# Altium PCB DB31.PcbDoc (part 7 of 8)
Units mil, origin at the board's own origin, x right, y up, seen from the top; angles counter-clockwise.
Board outline 3236.22 x 4456.69 mil, 8 copper layers (Top Layer, MidLayer1, MidLayer2, GND-Layer5, MidLayer3, VCC, MidLayer4, Bottom Layer), stack 61.8 mil thick; 226 components, 469 nets, 1815 pads, 1562 vias.
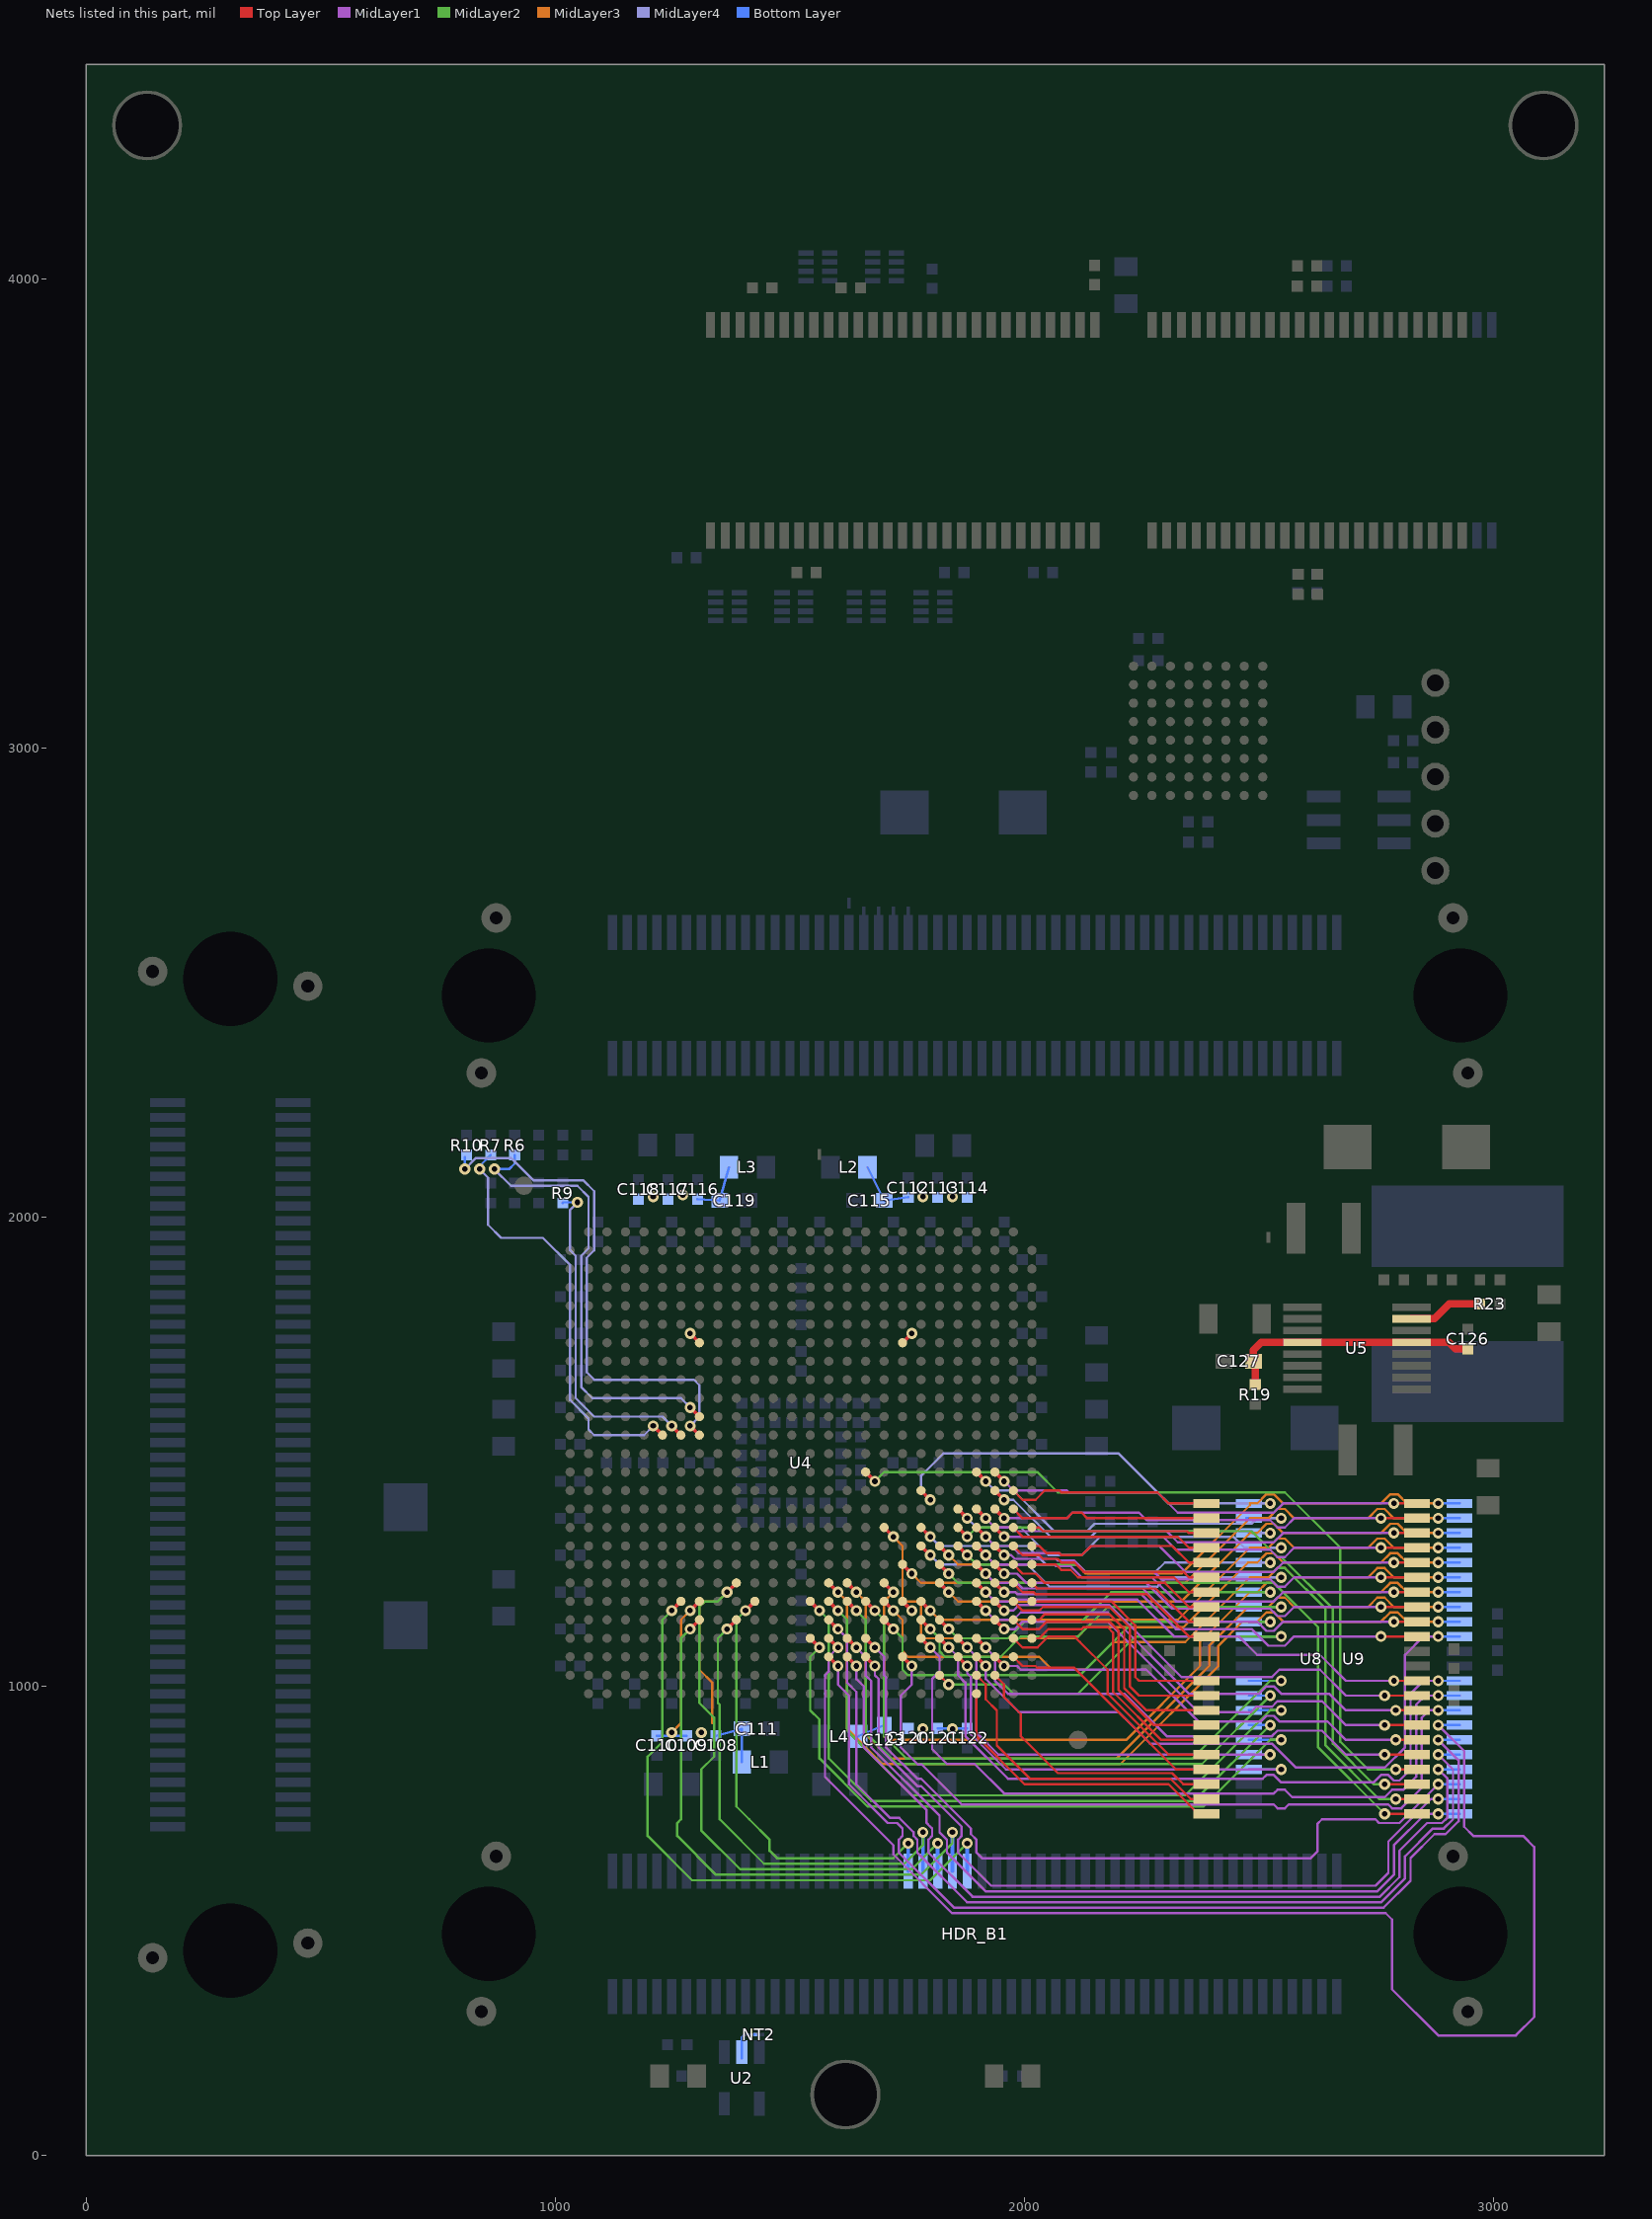
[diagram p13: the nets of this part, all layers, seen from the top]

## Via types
v1: diameter 23.62, hole 11.81, Top Layer to Bottom Layer, 947 vias
v2: diameter 23.62, hole 11.81, Top Layer to Bottom Layer, tented both sides, 476 vias
v3: diameter 27.56, hole 15.75, Top Layer to Bottom Layer, 138 vias
v4: diameter 23.62, hole 11.81, Top Layer to Bottom Layer, tented top, 1 vias

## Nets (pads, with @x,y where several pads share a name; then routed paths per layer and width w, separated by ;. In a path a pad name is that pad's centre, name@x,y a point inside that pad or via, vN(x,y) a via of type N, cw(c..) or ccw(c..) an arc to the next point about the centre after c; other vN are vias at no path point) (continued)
SRAM1_A3: U4.AD22 U9.4 | length 938
  Top Layer w7.87: U4.AD22@1858.27,1062.99 v1(1877.95,1043.3)
  MidLayer1 w5: v1(1877.95,1043.3) 1877.95,1027.56 1885.83,1019.68 1885.83,921.26 1885.83,909.45 1885.83,897.64 1960.63,822.83 v1(2547.24,822.83)
  Bottom Layer w5: U9.4@2478.44,822.83 v1(2547.24,822.83)
SRAM1_A4: U4.AC22 U9.5 | length 907.8
  Top Layer w7.87: U4.AC22@1858.27,1102.36 v1(1877.96,1082.67)
  MidLayer1 w5: v1(1877.96,1082.67) 1897.64,1062.99 1897.64,921.26 1897.64,909.45 1897.64,901.57 1944.88,854.33 v1(2523.62,854.33)
  Bottom Layer w5: U9.5@2478.44,854.32 v1(2523.62,854.33)
SRAM1_A5: U4.U20 U9.18 | length 840.9
  Top Layer w7.87: U4.U20@1779.53,1338.58 v1(1799.22,1318.9)
  MidLayer4 w5: v1(1799.22,1318.9) 1818.9,1299.21 2005.91,1299.21 2045.27,1259.84 2078.74,1259.84 2090.55,1259.84 2114.17,1259.84 2129.92,1244.09 2279.53,1244.09 2299.2,1263.77 v1(2523.83,1263.77)
  Bottom Layer w5: U9.18@2478.44,1263.77 v1(2523.83,1263.77) v1@2527.77,1263.77
SRAM1_A6: U4.T22 U9.19 | length 828.6
  Top Layer w7.87: U4.T22@1858.27,1377.95 v1(1877.96,1358.27)
  MidLayer4 w5: v1(1877.96,1358.27) 1897.64,1338.58 1992.13,1338.58 2051.18,1279.53 2078.74,1279.53 2090.55,1279.53 2122.05,1279.53 2161.42,1318.9 2444.88,1318.9 2468.5,1295.28 v1(2547.24,1295.28)
  Bottom Layer w5: U9.19@2478.44,1295.27 v1(2547.24,1295.28) v1@2551.18,1295.28
SRAM1_A7: U4.R24 U9.20 | length 683.4
  Top Layer w7.87: U4.R24@1937.01,1417.32 v1(1956.7,1397.64)
  MidLayer4 w5: v1(1956.7,1397.64) 1976.38,1397.64 2055.12,1318.9 2078.74,1318.9 2090.55,1318.9 2141.73,1318.9 2153.54,1330.71 2484.25,1330.71 2488.2,1326.76 v1(2523.83,1326.76)
  Bottom Layer w5: U9.20@2478.44,1326.76 v1(2523.83,1326.76) v1@2527.77,1326.76
SRAM1_A8: U4.P23 U9.21 | length 791.9
  Top Layer w7.87: U4.P23@1897.64,1456.69 v1(1917.33,1437.01)
  MidLayer4 w5: v1(1917.33,1437.01) 1937.01,1417.32 1976.38,1417.32 2062.99,1330.71 2078.74,1330.71 2090.55,1330.71 2133.86,1330.71 2149.61,1346.46 2484.25,1346.46 2496.06,1358.27 v1(2547.24,1358.27)
  Bottom Layer w5: U9.21@2472.44,1358.27 U9.21@2478.44,1358.26 v1(2547.24,1358.27) v1@2551.18,1358.27
SRAM1_A9: U4.R20 U9.22 | length 940.5
  Top Layer w7.87: U4.R20@1779.53,1417.32 v1(1799.22,1397.64)
  MidLayer4 w5: v1(1799.22,1397.64) 1779.53,1417.32 1779.53,1448.82 1826.77,1496.06 2078.74,1496.06 2090.55,1496.06 2200.79,1496.06 2307.1,1389.75 v1(2523.83,1389.75)
  Bottom Layer w5: U9.22@2478.44,1389.75 v1(2523.83,1389.75)
SRAM1_A10: U4.V21 U9.23 | length 1229.9
  Top Layer w7.87: U4.V21@1818.9,1299.21 v1(1838.59,1279.53)
  MidLayer3 w5: v1(1838.59,1279.53) 1858.27,1259.84 2078.74,1259.84 2090.55,1259.84 2110.24,1259.84 2129.92,1240.16 2334.65,1240.16 2480.33,1385.84 2480.33,1389.75 2496.27,1389.75 2515.96,1409.44 2531.7,1409.44 2551.38,1389.76 ; 2551.18,1389.76 2551.38,1389.76 ; v1(2881.9,1389.75) 2814.97,1389.75 2795.28,1409.45 2779.53,1409.45 2759.84,1389.76 2551.38,1389.76
  Bottom Layer w5: v1(2881.9,1389.75) U9.23@2927.25,1389.75
SRAM1_A11: U4.W19 U9.24 | length 1292.8
  Top Layer w7.87: U4.W19@1740.16,1259.84 v1(1759.84,1240.16)
  MidLayer3 w5: v1@1760.03,1239.97 1779.53,1220.47 2078.74,1220.47 2090.55,1220.47 2342.52,1220.47 2480.31,1358.27 2519.69,1358.27 2539.37,1377.95 2555.12,1377.95 2574.8,1358.27 2732.28,1358.27 2751.97,1377.95 2767.72,1377.95 2787.41,1358.26 v1(2881.9,1358.26)
  Bottom Layer w5: v1(2881.9,1358.26) U9.24@2927.25,1358.26
SRAM1_A12: U4.Y21 U9.25 | length 1217.6
  Top Layer w7.87: U4.Y21@1818.9,1220.47 v1(1838.58,1200.78)
  MidLayer3 w5: v1(1838.58,1200.78) 1858.27,1181.1 2078.74,1181.1 2090.55,1181.1 2334.67,1181.1 2480.33,1326.76 2496.27,1326.76 2515.96,1346.45 2531.7,1346.45 2551.38,1326.77 2759.84,1326.77 2779.53,1346.46 2795.28,1346.46 2814.97,1326.76 v1(2881.9,1326.76)
  Bottom Layer w5: v1(2881.9,1326.76) U9.25@2927.25,1326.76
SRAM1_A13: U4.AA20 U9.26 | length 1260.3
  Top Layer w7.87: U4.AA20@1779.53,1181.1 v1(1799.22,1161.41)
  MidLayer3 w5: v1(1799.22,1161.41) 1818.9,1141.73 2078.74,1141.73 2090.55,1141.73 2326.77,1141.73 2480.31,1295.28 2519.69,1295.28 2539.37,1314.96 2555.12,1314.96 2574.8,1295.28 2732.28,1295.28 2751.97,1314.96 2767.72,1314.96 2787.41,1295.27 v1(2881.9,1295.27)
  Bottom Layer w5: v1(2881.9,1295.27) U9.26@2927.25,1295.27
SRAM1_A14: U4.U18 U9.27 | length 1525.3
  Top Layer w7.87: U4.U18@1700.79,1338.58 v1(1720.47,1318.9)
  MidLayer3 w5: v1(1720.47,1318.9) 1740.16,1299.21 1740.16,1188.98 1748.03,1181.1 1771.65,1181.1 1779.53,1173.23 1779.53,1110.24 1787.4,1102.36 2078.74,1102.36 2090.55,1102.36 2110.24,1102.36 2133.86,1125.98 2338.58,1125.98 2476.37,1263.77 2496.27,1263.77 2515.96,1283.45 2531.7,1283.45 2551.38,1263.78 2759.84,1263.78 2779.53,1283.46 2795.28,1283.46 2814.97,1263.77 v1(2881.9,1263.77)
  Bottom Layer w5: v1(2881.9,1263.77) U9.27@2927.25,1263.77
SRAM1_A15: U4.AC17 U9.42 | length 1700
  Top Layer w7.87: U4.AC17@1661.42,1102.36 v1(1681.1,1082.67)
  MidLayer1 w5: v1(1681.1,1082.67) 1700.79,1062.99 1700.79,1023.62 1704.72,1019.68 1704.72,921.26 1704.72,909.45 1704.72,870.08 1771.65,803.15 1779.53,803.15 1885.83,696.85 1885.83,685.04 1897.64,673.23 1897.64,645.67 1909.45,633.86 2610.24,633.86 2624.26,647.88 2624.26,706.94 2633.86,716.54 2748.03,716.54 2755.91,708.66 2799.21,708.66 v1(2881.9,791.33)
  Bottom Layer w5: v1(2881.9,791.33) U9.42@2927.25,791.33
SRAM1_A16: U4.AD17 U9.43 | length 1724
  Top Layer w7.87: U4.AD17@1661.42,1062.99 v1(1681.1,1043.3)
  MidLayer1 w5: v1(1681.1,1043.3) 1681.1,1023.62 1688.98,1015.75 1688.98,921.26 1688.98,909.45 1688.98,870.08 1771.65,787.4 1779.53,787.4 1866.14,700.79 1866.14,681.1 1858.27,673.23 1858.27,645.67 1928.89,575.05 2748.28,575.05 2775.59,602.36 2775.59,669.29 2866.13,759.83 v1(2881.9,759.83)
  Bottom Layer w5: v1(2881.9,759.83) U9.43@2927.25,759.83
SRAM1_A17: U4.AC16 U9.44 | length 1776.8
  Top Layer w7.87: U4.AC16@1622.05,1102.36 v1(1641.73,1082.67)
  MidLayer1 w5: v1(1641.73,1082.67) 1661.42,1062.99 1661.42,1023.62 1673.23,1011.81 1673.23,921.26 1673.23,909.45 1673.23,870.08 1818.9,724.41 1818.9,688.98 1834.65,673.23 1834.65,645.67 1917.08,563.24 2752.21,563.24 2787.4,598.43 2787.4,661.42 2854.32,728.34 v1(2881.9,728.34)
  Bottom Layer w5: v1(2881.9,728.34) U9.44@2927.25,728.34
SRAM1_A18: U4.AA18 U9.28 | length 1440.2
  Top Layer w7.87: U4.AA18@1700.79,1181.1 v1(1720.47,1161.41)
  MidLayer3 w5: v1(1720.47,1161.41) 1740.16,1141.73 1740.16,1074.8 1751.97,1062.99 2031.5,1062.99 2059.05,1035.43 2078.74,1035.43 2090.55,1035.43 2129.92,1035.43 2188.98,1094.49 2342.52,1094.49 2480.31,1232.28 2519.69,1232.28 2539.37,1251.97 2555.12,1251.97 2574.8,1232.28 2732.28,1232.28 2751.97,1251.97 2767.72,1251.97 2787.41,1232.28 v1(2881.9,1232.27)
  Bottom Layer w5: v1(2881.9,1232.27) U9.28@2927.25,1232.27
SRAM1_D0: U4.AA14 U9.7 | length 1445.8
  Top Layer w7.87: U4.AA14@1543.31,1181.1 v1(1562.99,1161.41)
  MidLayer2 w5: v1(1562.99,1161.41) 1582.68,1141.73 1582.68,921.26 1582.68,909.45 1582.68,846.46 1673.23,755.91 2362.2,755.91 2523.6,917.3 v1(2523.83,917.3)
  Bottom Layer w5: U9.7@2478.44,917.31 v1(2523.83,917.3) v1@2527.77,917.3
SRAM1_D1: U4.AA15 U9.8 | length 1421.9
  Top Layer w7.87: U4.AA15@1582.68,1181.1 v1(1602.36,1161.41)
  MidLayer2 w5: v1(1602.36,1161.41) 1622.05,1141.73 1622.05,921.26 1622.05,909.45 1622.05,905.51 1759.84,767.72 2342.52,767.72 2523.62,948.82 v1(2547.24,948.82)
  Bottom Layer w5: U9.8@2478.44,948.81 v1(2547.24,948.82) v1@2551.18,948.82
SRAM1_D2: U4.AA16 U9.9 | length 1295.9
  Top Layer w7.87: U4.AA16@1622.05,1181.1 v1(1641.73,1161.41)
  MidLayer2 w5: v1(1641.73,1161.41) 1661.42,1141.73 1661.42,921.26 1661.42,909.45 1661.42,901.57 1728.35,834.65 2378.17,834.65 v1(2523.83,980.31) v1@2523.61,980.31
  Bottom Layer w5: U9.9@2478.44,980.31 v1(2523.83,980.31) v1@2527.77,980.31
SRAM1_D3: U4.AA17 U9.10 | length 1311
  Top Layer w7.87: U4.AA17@1661.42,1181.1 v1(1681.1,1161.41)
  MidLayer2 w5: v1(1681.1,1161.41) 1700.79,1141.73 1700.79,921.26 1700.79,909.45 1700.79,893.7 1748.03,846.46 2358.27,846.46 2523.62,1011.81 v1(2547.24,1011.81)
  Bottom Layer w5: U9.10@2478.44,1011.8 v1(2547.24,1011.81) v1@2551.18,1011.81
SRAM1_D4: U4.AE21 U9.13 | length 868
  Top Layer w5: U4.AE21@1818.9,1023.62 v1(1838.58,1003.94)
  MidLayer2 w5: v1(1838.58,1003.94) 1956.69,1003.94 1976.38,984.25 2078.74,984.25 2090.55,984.25 2114.17,984.25 2236.22,1106.3 v1(2547.24,1106.3)
  Bottom Layer w5: U9.13@2478.44,1106.29 v1(2547.24,1106.3) v1@2551.18,1106.3
SRAM1_D5: U4.AB18 U9.14 | length 1007.8
  Top Layer w7.87: U4.AB18@1700.79,1141.73 v1(1720.47,1122.04)
  MidLayer2 w5: v1(1720.47,1122.04) 1740.16,1102.36 1740.16,1035.43 1751.97,1023.62 2078.74,1023.62 2090.55,1023.62 2118.11,1023.62 2232.27,1137.79 v1(2523.83,1137.79)
  Bottom Layer w5: U9.14@2478.44,1137.79 v1(2523.83,1137.79) v1@2527.77,1137.79
SRAM1_D6: U4.AB20 U9.15 | length 933.2
  Top Layer w7.87: U4.AB20@1779.53,1141.73 v1(1799.21,1122.04)
  MidLayer2 w5: v1(1799.21,1122.04) 1818.9,1102.36 1818.9,1074.8 1830.71,1062.99 1948.82,1062.99 1992.13,1106.3 2078.74,1106.3 2090.55,1106.3 2114.17,1106.3 2177.17,1169.29 v1(2547.24,1169.29)
  Bottom Layer w5: U9.15@2478.44,1169.28 v1(2547.24,1169.29) v1@2551.18,1169.29
SRAM1_D7: U4.AB21 U9.16 | length 811.3
  Top Layer w7.87: U4.AB21@1818.9,1141.73 v1(1838.58,1122.04)
  MidLayer2 w5: v1(1838.58,1122.04) 1858.27,1102.36 1964.57,1102.36 2000,1137.8 2078.74,1137.8 2090.55,1137.8 2122.05,1137.8 2185.04,1200.79 v1@2523.83,1200.79
  Bottom Layer w5: U9.16@2478.44,1200.78 v1(2523.83,1200.78) v1@2527.77,1200.78
SRAM1_D8: U4.Y18 U9.29 | length 1765.9
  Top Layer w7.87: U4.Y18@1700.79,1220.47 v1(1720.47,1200.78)
  MidLayer3 w5: v1(1720.47,1200.78) 1700.79,1181.1 1700.79,921.26 1700.79,909.45 1700.79,893.7 1708.66,885.83 2216.54,885.83 2374.02,1043.31 2374.02,1094.49 2480.3,1200.78 2496.27,1200.78 2515.96,1220.46 2531.7,1220.46 2551.38,1200.79 2759.84,1200.79 2779.53,1220.47 2795.28,1220.47 2814.97,1200.78 v1(2881.9,1200.78)
  Bottom Layer w5: v1(2881.9,1200.78) U9.29@2927.25,1200.78
SRAM1_D9: U4.Y16 U9.30 | length 1817.9
  Top Layer w7.87: U4.Y16@1622.05,1220.47 v1(1641.73,1200.78)
  MidLayer3 w5: v1(1641.73,1200.78) 1661.42,1181.1 1661.42,921.26 1661.42,909.45 1661.42,897.64 1712.6,846.46 2196.85,846.46 2393.7,1043.31 2393.7,1086.61 2476.38,1169.29 2519.69,1169.29 2539.37,1188.98 2555.12,1188.98 2574.8,1169.29 2732.28,1169.29 2751.97,1188.98 2767.72,1188.98 2787.41,1169.29 v1(2881.9,1169.28)
  Bottom Layer w5: v1(2881.9,1169.28) U9.30@2927.25,1169.28
SRAM1_D10: U4.Y15 U9.31 | length 1847.1
  Top Layer w7.87: U4.Y15@1582.68,1220.47 v1(1602.36,1200.78)
  MidLayer3 w5: v1(1602.36,1200.78) 1622.05,1181.1 1622.05,921.26 1622.05,909.45 1696.85,834.65 2204.72,834.65 2413.39,1043.31 2413.39,1086.61 2464.56,1137.79 2496.27,1137.79 2515.96,1157.47 2531.7,1157.47 2551.38,1137.8 2759.84,1137.8 2779.53,1157.48 2795.28,1157.48 2814.97,1137.79 v1(2881.9,1137.79)
  Bottom Layer w5: v1(2881.9,1137.79) U9.31@2927.25,1137.79
SRAM1_D11: U4.AD23 U9.32 | length 1379
  Top Layer w7.87: U4.AD23@1897.64,1062.99 v1(1917.33,1043.3)
  MidLayer1 w5: v1(1917.33,1043.3) 1917.33,1015.75 1988.19,944.88 2078.74,944.88 2090.55,944.88 2200.79,944.88 2267.72,877.95 2527.56,877.95 2578.75,826.76 2767.71,826.76 2811.02,870.08 2811.02,1066.93 2850.39,1106.3 2858.27,1106.3 2862.59,1106.3 ; 2858.28,1106.29 v1(2881.9,1106.29)
  Bottom Layer w5: v1(2881.9,1106.29) U9.32@2927.25,1106.29
SRAM1_D12: U4.AC21 U9.35 | length 1526.1
  Top Layer w7.87: U4.AC21@1818.9,1102.36 v1(1838.59,1082.67)
  MidLayer1 w5: v1(1838.59,1082.67) 1858.27,1062.99 1858.27,1023.62 1874.02,1007.87 1874.02,921.26 1874.02,909.45 1874.02,893.7 1964.57,803.15 2507.87,803.15 2515.75,811.02 2531.5,811.02 2547.24,795.28 2744.09,795.27 2759.84,811.02 2775.6,811.02 2787.4,799.21 2799.21,799.21 2822.83,822.83 2822.83,984.25 2850.39,1011.81 2862.2,1011.81 ; 2862.21,1011.8 v1(2881.9,1011.8)
  Bottom Layer w5: v1(2881.9,1011.8) U9.35@2927.25,1011.8
SRAM1_D13: U4.AC20 U9.36 | length 1611.7
  Top Layer w7.87: U4.AC20@1779.53,1102.36 v1(1799.22,1082.67)
  MidLayer1 w5: v1(1799.22,1082.67) 1818.9,1062.99 1818.9,1031.5 1803.15,1015.75 1803.15,921.26 1803.15,909.45 1803.15,866.14 1834.65,834.65 1893.7,834.65 1956.69,771.65 2531.5,771.65 2539.37,779.53 2555.12,779.53 2570.87,763.78 2767.71,763.77 2783.46,779.52 2807.08,779.52 2834.65,807.09 2834.65,960.63 2854.33,980.32 2862.2,980.32 v1(2881.9,980.31)
  Bottom Layer w5: v1(2881.9,980.31) U9.36@2927.25,980.31
SRAM1_D14: U4.AD19 U9.37 | length 1636.3
  Top Layer w7.87: U4.AD19@1740.16,1062.99 v1(1759.84,1043.3)
  MidLayer1 w5: v1(1759.84,1043.3) 1759.84,1003.94 1736.22,980.32 1736.22,921.26 1736.22,909.45 1736.22,870.08 1772.88,833.42 1780.75,833.42 1827.76,786.42 1866.14,748.03 2531.5,748.03 2539.37,740.16 2555.12,740.16 2562.99,748.03 2775.59,748.03 2783.46,740.16 2803.15,740.16 2846.46,783.46 2846.46,933.07 2862.2,948.82 v1(2881.9,948.81)
  Bottom Layer w5: v1(2881.9,948.81) U9.37@2927.25,948.81
SRAM1_D15: U4.AC15 U9.38 | length 2984.3
  Top Layer w7.87: U4.AC15@1582.68,1102.36 v1(1602.36,1082.67)
  MidLayer1 w5: v1(1602.36,1082.67) 1582.68,1062.99 1582.68,1031.5 1574.8,1023.62 1574.8,921.26 1574.8,909.45 1574.8,807.09 1720.47,661.42 1720.47,641.73 1845.47,516.73 2769.68,516.73 2783.46,502.95 2783.46,354.33 2881.89,255.91 3047.24,255.91 3086.61,295.28 3086.61,657.48 3062.99,681.1 2956.69,681.1 2937.01,700.79 2937.01,862.2 v1(2881.9,917.31)
  Bottom Layer w5: v1(2881.9,917.31) U9.38@2927.25,917.31
SRAM1_NBHE: U4.AB15 U9.40 | length 2068.3
  Top Layer w7.87: U4.AB15@1582.68,1141.73 v1(1602.36,1122.04)
  MidLayer1 w5: v1(1602.36,1122.04) 1622.05,1102.36 1622.05,1007.87 1641.73,988.19 1641.73,921.26 1641.73,909.45 1641.73,791.34 1713.58,719.49 1733.27,719.49 1763.78,688.98 1763.78,681.1 1771.65,673.23 1771.65,645.67 1877.21,540.11 2760.58,540.11 2811.02,590.55 2811.02,637.79 2870.08,696.85 2893.7,696.85 2913.39,716.54 2913.39,822.83 v1(2881.9,854.32)
  Bottom Layer w5: v1(2881.9,854.32) U9.40@2927.25,854.32
SRAM1_NBLE: U4.AD15 U9.39 | length 2079.8
  Top Layer w7.87: U4.AD15@1582.68,1062.99 v1(1602.36,1043.3)
  MidLayer1 w5: v1(1602.36,1043.3) 1602.36,1003.93 1620.15,986.15 1625.98,980.31 1625.98,921.26 1625.98,909.45 1625.98,791.34 1708.66,708.66 1728.35,708.66 1740.16,696.85 1740.16,681.1 1732.28,673.23 1732.28,645.67 1849.41,528.54 2765.75,528.54 2822.83,585.63 2822.83,633.86 2874.02,685.04 2897.64,685.04 2925.2,712.6 2925.2,842.52 v1(2881.9,885.82)
  Bottom Layer w5: v1(2881.9,885.82) U9.39@2927.25,885.82
SRAM1_NCS: U4.AC14 U9.6 | length 1438.5
  Top Layer w7.87: U4.AC14@1543.31,1102.36 v1(1562.99,1082.67)
  MidLayer2 w5: v1(1562.99,1082.67) 1543.31,1062.99 1543.31,948.82 1562.99,929.13 1562.99,921.26 1562.99,909.45 1562.99,846.46 1665.35,744.09 2381.89,744.09 2523.62,885.83 v1(2547.24,885.83)
  Bottom Layer w5: U9.6@2478.44,885.82 v1(2547.24,885.83) v1@2551.18,885.83
SRAM1_NOE: U4.AD16 U9.41 | length 1899.5
  Top Layer w7.87: U4.AD16@1622.05,1062.99 v1(1641.73,1043.3)
  MidLayer1 w5: v1(1641.73,1043.3) 1641.74,1015.75 1657.48,1000 1657.48,921.26 1657.48,909.45 1657.48,870.08 1791.34,736.22 1791.34,708.66 1799.21,700.79 1803.15,696.85 1803.15,681.1 1795.28,673.23 1795.28,645.67 1889.27,551.67 2757.38,551.67 2799.21,593.5 2799.21,649.61 2858.27,708.66 2889.76,708.66 2901.57,720.47 2901.57,803.15 v1(2881.9,822.83)
  Bottom Layer w5: v1(2881.9,822.83) U9.41@2927.25,822.83
SRAM1_NWE: U4.V20 U9.17 | length 884.5
  Top Layer w7.87: U4.V20@1779.53,1299.21 v1(1799.22,1279.53)
  MidLayer4 w5: v1(1799.22,1279.53) 1818.9,1259.84 2005.91,1259.84 2053.15,1212.6 2078.74,1212.6 2090.55,1212.6 2283.46,1212.6 2303.15,1232.28 v1(2547.24,1232.28)
  Bottom Layer w5: U9.17@2478.44,1232.28 v1(2547.24,1232.28) v1@2551.18,1232.28
SRAM2_A0: U4.W21 U8.1 | length 1387.9
  Top Layer w5: v1(2767.69,728.34) U8.1@2836.71,728.34
  Top Layer w7.87: U4.W21@1818.9,1259.84 v1(1838.59,1240.16)
  MidLayer2 w5: v1(1838.59,1240.16) 1858.27,1220.47 2078.74,1220.47 2090.55,1220.47 2531.5,1220.47 2625.98,1125.98 2625.98,870.08 v1(2767.69,728.34)
SRAM2_A1: U4.V22 U8.2 | length 1379
  Top Layer w5: v1(2791.34,759.84) U8.2@2836.71,759.83
  Top Layer w7.87: U4.V22@1858.27,1299.21 v1(1877.96,1279.53)
  MidLayer2 w5: v1(1877.96,1279.53) 1897.64,1259.84 2078.74,1259.84 2090.55,1259.84 2114.17,1259.84 2129.92,1244.09 2531.5,1244.09 2539.37,1251.97 2555.12,1251.97 2641.73,1165.35 2641.73,874.02 2755.91,759.84 v1(2791.34,759.84)
SRAM2_A2: U4.U22 U8.3 | length 1389.8
  Top Layer w5: v1(2767.69,791.34) U8.3@2836.71,791.33
  Top Layer w7.87: U4.U22@1858.27,1338.58 v1(1877.96,1318.9)
  MidLayer2 w5: v1(1877.96,1318.9) 1897.64,1338.58 2025.59,1338.58 2033.47,1330.71 2078.74,1330.71 2090.55,1330.71 2484.25,1330.71 2539.37,1275.59 2547.24,1275.59 2657.48,1165.35 2657.48,877.95 2744.1,791.34 v1(2767.69,791.34)
SRAM2_A3: U4.P17 U8.4 | length 1696.3
  Top Layer w5: v1(2791.34,822.83) U8.4@2836.71,822.83
  Top Layer w7.87: U4.P17@1661.42,1456.69 v1(1681.1,1437.01)
  MidLayer2 w5: v1(1681.1,1437.01) 1700.79,1456.69 2027.56,1456.69 2070.87,1413.39 2078.74,1413.39 2090.55,1413.39 2555.12,1413.39 2673.23,1295.28 2673.23,881.89 2732.28,822.83 v1(2791.34,822.83)
SRAM2_A4: U4.AC23 U8.5 | length 1101.6
  Top Layer w5: v1(2767.69,854.33) U8.5@2836.71,854.32
  Top Layer w7.87: U4.AC23@1897.64,1102.36 v1(1917.33,1082.67)
  MidLayer1 w5: v1@2759.84,854.31 2685.04,854.31 2633.86,905.51 2539.37,905.51 2527.56,893.7 2303.15,893.7 2212.6,984.25 2090.55,984.25 2078.74,984.25 1964.57,984.25 1937.01,1011.81 1937.01,1062.99 ; 1937.01,1062.99 v1(1917.33,1082.67) 1937.01,1062.99
SRAM2_A5: U4.U23 U8.18 | length 1002.7
  Top Layer w5: v1@2787.4,1263.77 U8.18@2836.71,1263.77
  Top Layer w7.87: U4.U23@1897.64,1338.58 v1(1917.33,1318.9)
  MidLayer1 w5: v1(1917.33,1318.9) 1937.01,1299.21 1972.44,1299.21 1988.19,1283.46 2074.8,1283.46 2078.74,1279.53 2090.55,1279.53 2122.05,1279.53 2141.73,1299.21 2287.4,1299.21 2342.52,1244.09 2531.5,1244.09 2551.18,1263.78 v1(2787.4,1263.78)
SRAM2_A6: U4.U24 U8.19 | length 933.9
  Top Layer w5: v1(2759.84,1295.28) U8.19@2836.71,1295.27
  Top Layer w7.87: U4.U24@1937.01,1338.58 v1(1956.7,1318.9)
  MidLayer1 w5: v1(1956.7,1318.9) 2078.74,1318.9 2090.55,1318.9 2295.28,1318.9 2322.83,1291.34 2523.62,1291.34 2539.37,1275.59 2555.12,1275.59 2574.8,1295.28 v1(2759.84,1295.28)
SRAM2_A7: U4.T23 U8.20 | length 976.6
  Top Layer w5: v1(2787.4,1326.77) U8.20@2836.71,1326.76
  Top Layer w7.87: U4.T23@1897.64,1377.95 v1(1917.33,1358.27)
  MidLayer1 w5: v1(1917.33,1358.27) 1937.01,1338.58 1972.44,1338.58 1980.32,1330.71 2078.74,1330.71 2090.55,1330.71 2303.15,1330.71 2326.77,1307.09 2531.5,1307.09 2551.18,1326.77 v1(2787.4,1326.77)
SRAM2_A8: U4.T24 U8.21 | length 933.9
  Top Layer w5: v1(2759.84,1358.27) U8.21@2836.71,1358.26
  Top Layer w7.87: U4.T24@1937.01,1377.95 v1(1956.7,1358.27)
  MidLayer1 w5: v1(1956.7,1358.27) 2078.74,1358.27 2090.55,1358.27 2102.36,1370.08 2244.09,1370.08 2259.84,1354.33 2523.62,1354.33 2539.37,1338.58 2555.12,1338.58 2574.8,1358.27 v1(2759.84,1358.27)
SRAM2_A9: U4.P24 U8.22 | length 943.7
  Top Layer w5: v1(2787.4,1389.76) U8.22@2836.71,1389.76
  Top Layer w7.87: U4.P24@1937.01,1456.69 v1(1956.7,1437.01)
  MidLayer1 w5: v1(1956.7,1437.01) 1976.38,1417.32 2078.74,1417.32 2090.55,1417.32 2094.49,1413.39 2283.46,1413.39 2326.77,1370.08 2531.5,1370.08 2551.18,1389.76 v1(2787.4,1389.76)
SRAM2_A10: U4.R25 U8.23 | length 439.2
  Top Layer w5: U4.R25@1976.38,1417.32 1996.06,1397.64 2023.62,1397.64 2043.31,1417.32 2074.8,1417.32 2078.74,1413.39 2090.55,1413.39 2283.46,1413.39 2307.1,1389.76 U8.23@2387.89,1389.76
SRAM2_A11: U4.T25 U8.24 | length 429.5
  Top Layer w5: U4.T25@1976.38,1377.95 1996.07,1358.27 2078.74,1358.27 2090.55,1358.27 2102.36,1370.08 2122.05,1370.08 2133.87,1358.26 U8.24@2387.89,1358.26
SRAM2_A12: U4.U26 U8.25 | length 377
  Top Layer w5: U4.U26@2015.75,1338.58 2031.5,1338.58 2039.37,1330.71 2078.74,1330.71 2090.55,1330.71 2346.46,1330.71 2350.4,1326.76 U8.25@2387.89,1326.76
SRAM2_A13: U4.U25 U8.26 | length 429.5
  Top Layer w5: U4.U25@1976.38,1338.58 1996.06,1318.9 2078.74,1318.9 2090.55,1318.9 2326.77,1318.9 2350.4,1295.27 U8.26@2387.89,1295.27
SRAM2_A14: U4.V26 U8.27 | length 403.1
  Top Layer w5: U4.V26@2015.75,1299.21 2031.5,1299.21 2047.24,1283.46 2074.8,1283.46 2078.74,1279.53 2090.55,1279.53 2122.05,1279.53 2141.73,1299.21 2314.96,1299.21 2350.4,1263.77 U8.27@2387.89,1263.77
SRAM2_A15: U4.AE24 U8.42 | length 590.9
  Top Layer w5: U4.AE24@1937.01,1023.62 1956.69,1003.94 1956.69,976.38 1992.13,940.95 1992.13,921.26 1992.13,909.45 1992.13,893.7 2070.87,814.96 2314.96,814.96 2338.59,791.33 U8.42@2387.89,791.33
SRAM2_A16: U4.AE23 U8.43 | length 661.8
  Top Layer w5: U4.AE23@1897.64,1023.62 1917.32,1003.94 1917.32,972.44 1940.94,948.82 1940.94,921.26 1940.94,909.45 1940.94,874.02 2011.81,803.15 2311.02,803.15 2354.34,759.83 U8.43@2387.89,759.83
SRAM2_A17: U4.AF23 U8.44 | length 649.3
  Top Layer w5: U4.AF23@1897.64,984.25 1897.64,921.26 1897.64,909.45 1897.64,893.7 2000,791.34 2307.09,791.34 2370.09,728.34 U8.44@2387.89,728.34
SRAM2_A18: U4.V25 U8.28 | length 439.2
  Top Layer w5: U4.V25@1976.38,1299.21 1996.06,1279.53 2031.5,1279.53 2039.37,1271.65 2070.87,1271.65 2078.74,1263.78 2090.55,1263.78 2106.3,1263.78 2125.98,1244.09 2338.58,1244.09 2350.4,1232.28 U8.28@2387.89,1232.28
SRAM2_D0: U4.AB24 U8.7 | length 1017.6
  Top Layer w5: v1(2767.69,917.32) U8.7@2836.71,917.32
  Top Layer w7.87: U4.AB24@1937.01,1141.73 v1(1956.7,1122.04)
  MidLayer1 w5: v1(1956.7,1122.04) 1980.31,1122.04 1996.06,1137.8 2078.74,1137.8 2094.49,1137.8 2177.17,1137.8 2370.08,944.88 2482.35,944.88 2494.16,956.69 2527.58,956.69 2539.11,968.23 2539.11,968.5 2633.86,968.5 2685.06,917.3 v1@2759.84,917.3
SRAM2_D1: U4.AA23 U8.8 | length 1057.4
  Top Layer w5: v1(2791.34,948.82) U8.8@2836.71,948.81
  Top Layer w7.87: U4.AA23@1897.64,1181.1 v1(1917.33,1161.41)
  MidLayer1 w5: v1(1917.33,1161.41) 1937.01,1141.73 1976.38,1141.73 1992.13,1157.48 2078.74,1157.48 2094.49,1157.48 2177.17,1157.48 2350.39,984.25 2500,984.25 2515.75,1000 2531.5,1000 2547.24,984.25 2649.61,984.25 2685.04,948.83 v1@2787.41,948.83
SRAM2_D2: U4.AA24 U8.9 | length 997.9
  Top Layer w5: v1(2767.69,980.31) U8.9@2836.71,980.31
  Top Layer w7.87: U4.AA24@1937.01,1181.1 v1(1956.7,1161.41)
  MidLayer1 w5: v1(1956.7,1161.41) 1976.38,1161.42 1988.19,1173.23 2078.74,1173.23 2090.55,1173.23 2181.1,1173.23 2334.65,1019.68 2527.56,1019.68 2543.31,1035.43 2629.92,1035.43 2685.04,980.32 ; 2685.04,980.29 v1@2759.84,980.29
SRAM2_D3: U4.Y23 U8.10 | length 1028.8
  Top Layer w5: v1(2787.4,1011.81) U8.10@2836.71,1011.8
  Top Layer w7.87: U4.Y23@1897.64,1220.47 v1(1917.33,1200.78)
  MidLayer1 w5: v1(1917.33,1200.78) 1937.01,1181.1 1976.38,1181.1 1980.32,1185.04 2078.74,1185.04 2090.55,1185.04 2240.16,1185.04 2318.9,1106.3 2456.69,1106.3 2496.06,1066.93 2629.92,1066.93 2685.03,1011.82 v1(2787.4,1011.81)
SRAM2_D4: U4.Y24 U8.13 | length 963.3
  Top Layer w5: v1(2759.84,1106.3) U8.13@2836.71,1106.29
  Top Layer w7.87: U4.Y24@1937.01,1220.47 v1(1956.7,1200.78)
  MidLayer1 w5: v1(1956.7,1200.78) 1980.32,1200.79 1984.25,1196.85 2078.74,1196.85 2090.55,1196.85 2248.03,1196.85 2322.83,1122.05 2484.25,1122.05 2519.68,1086.62 2555.11,1086.62 2574.79,1106.31 v1(2759.84,1106.3)
SRAM2_D5: U4.W23 U8.14 | length 1005.9
  Top Layer w5: v1(2787.4,1137.8) U8.14@2836.71,1137.79
  Top Layer w7.87: U4.W23@1897.64,1259.84 v1(1917.33,1240.16)
  MidLayer1 w5: v1(1917.33,1240.16) 1937.01,1220.47 1984.25,1220.47 1996.06,1208.66 2078.74,1208.66 2090.55,1208.66 2251.97,1208.66 2322.83,1137.8 2496.06,1137.8 2515.75,1118.11 2531.49,1118.11 2551.17,1137.8 ; 2551.17,1137.8 v1(2787.4,1137.8)
SRAM2_D6: U4.W24 U8.15 | length 953.5
  Top Layer w5: v1(2759.84,1169.29) U8.15@2836.71,1169.28
  Top Layer w7.87: U4.W24@1937.01,1259.84 v1(1956.7,1240.16)
  MidLayer1 w5: v1(1956.7,1240.16) 1984.26,1240.16 2003.94,1220.47 2078.74,1220.47 2090.55,1220.47 2259.84,1220.47 2314.95,1165.36 2523.61,1165.36 2539.36,1149.61 2555.11,1149.61 2574.79,1169.3 v1(2759.84,1169.29)
SRAM2_D7: U4.V23 U8.16 | length 996.1
  Top Layer w5: v1(2787.4,1200.79) U8.16@2836.71,1200.78
  Top Layer w7.87: U4.V23@1897.64,1299.21 v1(1917.33,1279.53)
  MidLayer1 w5: v1(1917.33,1279.53) 1937.01,1259.84 2062.99,1259.84 2066.93,1255.91 2078.74,1255.91 2090.55,1255.91 2098.43,1255.91 2122.05,1232.28 2271.65,1232.28 2322.83,1181.1 2531.49,1181.1 ; 2531.49,1181.11 2551.17,1200.8 ; 2551.17,1200.8 v1(2787.4,1200.79)
SRAM2_D8: U4.W26 U8.29 | length 396.6
  Top Layer w5: U4.W26@2015.75,1259.84 2066.93,1259.84 2078.74,1248.03 2090.55,1248.03 2098.43,1248.03 2114.17,1232.28 2318.9,1232.28 2350.4,1200.78 U8.29@2387.89,1200.78
SRAM2_D9: U4.W25 U8.30 | length 449
  Top Layer w5: U4.W25@1976.38,1259.84 1996.06,1240.16 2023.62,1240.16 2043.31,1220.47 2078.74,1220.47 2090.55,1220.47 2299.21,1220.47 2350.4,1169.28 U8.30@2387.89,1169.28
SRAM2_D10: U4.Y26 U8.31 | length 406.4
  Top Layer w5: U4.Y26@2015.75,1220.47 2027.56,1208.66 2078.74,1208.66 2090.55,1208.66 2279.53,1208.66 2350.4,1137.79 U8.31@2387.89,1137.79
SRAM2_D11: U4.Y25 U8.32 | length 458.8
  Top Layer w5: U4.Y25@1976.38,1220.47 1996.06,1200.79 2019.68,1200.79 2023.62,1196.85 2078.74,1196.85 2090.55,1196.85 2259.84,1196.85 2350.4,1106.29 U8.32@2387.89,1106.29
SRAM2_D12: U4.AA26 U8.35 | length 506.8
  Top Layer w5: U4.AA26@2015.75,1181.1 2078.74,1181.1 2090.55,1181.1 2185.04,1181.1 2236.22,1129.92 2236.22,1019.68 2244.1,1011.8 U8.35@2387.89,1011.8
SRAM2_D13: U4.AA25 U8.36 | length 575
  Top Layer w5: U4.AA25@1976.38,1181.1 1996.06,1161.42 2031.5,1161.42 2039.37,1169.29 2078.74,1169.29 2090.55,1169.29 2181.1,1169.29 2224.41,1125.99 2224.41,1000 2244.1,980.31 U8.36@2387.89,980.31
SRAM2_D14: U4.AB26 U8.37 | length 535.6
  Top Layer w5: U4.AB26@2015.75,1141.73 2031.5,1141.73 2043.31,1153.54 2078.74,1153.54 2090.55,1153.54 2181.1,1153.54 2212.6,1122.05 2212.6,996.06 2259.85,948.81 U8.37@2387.89,948.81
SRAM2_D15: U4.AB25 U8.38 | length 591.3
  Top Layer w5: U4.AB25@1976.38,1141.73 1996.06,1122.05 2031.5,1122.05 2047.24,1137.8 2078.74,1137.8 2090.55,1137.8 2181.1,1137.8 2200.79,1118.11 2200.79,992.13 2275.6,917.32 U8.38@2387.89,917.32
SRAM2_NBHE: U4.AC25 U8.40 | length 563.8
  Top Layer w5: U4.AC25@1976.38,1102.36 1996.06,1082.68 2027.56,1082.68 2051.18,1106.3 2078.74,1106.3 2090.55,1106.3 2106.3,1106.3 2118.11,1094.49 2177.17,1035.43 2177.17,984.25 2307.09,854.32 U8.40@2387.89,854.32
SRAM2_NBLE: U4.AC26 U8.39 | length 555.2
  Top Layer w5: U4.AC26@2015.75,1102.36 2031.49,1102.36 2051.18,1122.05 2078.74,1122.05 2090.55,1122.05 2122.05,1122.05 2125.98,1125.98 2177.17,1125.98 2188.98,1114.17 2188.98,988.19 2291.35,885.82 U8.39@2387.89,885.82
SRAM2_NCS: U4.AD24 U8.6 | length 978.9
  Top Layer w5: v1(2791.34,885.83) U8.6@2836.71,885.82
  Top Layer w7.87: U4.AD24@1937.01,1062.99 v1(1956.7,1043.3)
  MidLayer1 w5: v1(1956.7,1043.3) 1984.25,1043.31 1992.12,1035.43 2078.74,1035.43 2090.55,1035.43 2259.84,1035.43 2370.08,925.2 2503.93,925.2 2515.75,937.01 2531.5,937.01 2543.31,925.2 2645.67,925.2 2685.03,885.83 v1@2787.41,885.83
SRAM2_NOE: U4.AD25 U8.41 | length 511
  Top Layer w5: U4.AD25@1976.38,1062.99 1996.06,1043.31 2023.62,1043.31 2027.56,1039.37 2078.74,1039.37 2090.55,1039.37 2106.3,1039.37 2322.84,822.83 U8.41@2387.89,822.83
SRAM2_NWE: U4.V24 U8.17 | length 943.7
  Top Layer w5: v1(2759.84,1232.28) U8.17@2836.71,1232.28
  Top Layer w7.87: U4.V24@1937.01,1299.21 v1(1956.7,1279.53)
  MidLayer1 w5: v1(1956.7,1279.53) 1971.46,1279.53 1979.33,1271.66 2066.93,1271.66 2070.87,1267.72 2078.74,1267.72 2090.55,1267.72 2106.3,1267.72 2129.92,1244.09 2275.59,1244.09 2291.33,1228.35 2523.61,1228.35 2539.36,1212.61 2555.11,1212.61 2574.79,1232.29 v1(2759.84,1232.28)
STATUS_LED: NT2.1 U2.2 | length 74.3
  Bottom Layer w5: U2.2@1397.64,207.68 U2.2@1397.64,220.47 1397.64,251.97 1403.54,257.87 NT2.1@1425.2,257.87
SW0: HDR_B1.42 U4.AA11 | length 951.1
  Top Layer w7.87: v1(1405.51,1161.41) U4.AA11@1425.2,1181.1
  MidLayer2 w5: v1(1405.51,1161.41) 1385.83,1141.73 1385.83,921.26 1385.83,909.45 1385.83,744.09 1413.39,716.54 1456.69,673.23 1456.69,649.61 1472.44,633.86 1720.47,633.86 v2(1751.97,665.35)
  Bottom Layer w7.87: HDR_B1.42@1751.97,606.3 v2(1751.97,665.35)
SW1: HDR_B1.44 U4.AB10 | length 1041.9
  Top Layer w7.87: v1(1366.14,1122.04) U4.AB10@1385.83,1141.73
  MidLayer2 w5: v1(1366.14,1122.04) 1346.46,1102.36 1346.46,964.56 1350.39,960.63 1350.39,921.26 1350.39,909.45 1350.39,716.54 1444.88,622.05 1744.09,622.05 1783.46,661.42 v2(1783.46,688.98)
  Bottom Layer w7.87: HDR_B1.44@1783.47,606.3 v2(1783.46,688.98)
SW2: HDR_B1.46 U4.Y10 | length 1552.4
  Top Layer w7.87: v1(1366.14,1200.78) U4.Y10@1385.83,1220.47
  MidLayer2 w5: v1(1366.14,1200.78) 1346.46,1181.1 1318.9,1181.1 1307.09,1169.29 1307.09,964.57 1338.58,933.07 1338.58,921.26 1338.58,909.45 1338.58,850.39 1311.02,822.83 1311.02,692.91 1393.7,610.24 1759.84,610.24 v2(1814.96,665.35)
  MidLayer3 w5: 1334.64,921.26 1334.64,1007.87 1307.09,1035.43 1307.09,1169.29 1318.9,1181.1 1346.46,1181.1 v1(1366.14,1200.78)
  Bottom Layer w7.87: HDR_B1.46@1814.96,606.3 v2(1814.96,665.35)
SW3: HDR_B1.48 U4.AB8 | length 1235.1
  Top Layer w7.87: v1(1287.4,1122.04) U4.AB8@1307.09,1141.73
  MidLayer2 w5: v1(1287.4,1122.04) 1267.72,1102.36 1267.72,921.26 1267.72,909.45 1267.72,716.54 1259.84,708.66 1259.84,681.1 1342.52,598.43 1779.53,598.43 1846.46,665.35 v2(1846.46,688.98)
  Bottom Layer w7.87: HDR_B1.48@1846.46,606.3 v2(1846.46,688.98)
SW4: HDR_B1.50 U4.AA7 | length 1341.3
  Top Layer w7.87: v1(1248.03,1161.41) U4.AA7@1267.72,1181.1
  MidLayer2 w5: v1(1248.03,1161.41) 1228.35,1141.73 1228.35,921.26 1228.35,909.45 1228.35,881.89 1196.85,850.39 1196.85,681.1 1291.34,586.61 1799.21,586.61 v2(1877.95,665.35)
  Bottom Layer w7.87: HDR_B1.50@1877.96,606.3 v2(1877.95,665.35)
TCK: R7.2 U4.M6 | length 921.8
  Top Layer w7.87: v1(1208.66,1555.12) U4.M6@1228.35,1535.43
  MidLayer4 w5: v1(838.58,2102.36) 856.75,2084.19 856.75,1983.59 884.44,1955.9 973.23,1955.9 1031.5,1897.64 1031.5,1610.24 1070.87,1570.87 1070.87,1547.24 1082.68,1535.43 1188.98,1535.43 v1(1208.66,1555.12)
  Bottom Layer w5: v1(838.58,2102.36) 838.58,2108.74 R7.2@862.2,2132.36
TDI: R10.2 U4.M8 | length 1107.3
  Top Layer w7.87: v1(1287.4,1555.12) U4.M8@1307.09,1535.43
  MidLayer4 w5: v1(807.09,2102.36) 830.71,2125.98 905.51,2125.98 952.76,2078.74 1059.06,2078.74 1082.68,2055.12 1082.68,1929.13 1066.93,1913.39 1066.93,1669.29 1082.68,1653.54 1295.28,1653.54 1307.09,1641.73 1307.09,1574.8 v1(1287.4,1555.12)
  Bottom Layer w5: v1(807.09,2102.36) R10.2@807.09,2128.42
TDO: R9.2 U4.M7 | length 717.9
  Top Layer w7.87: v1(1248.03,1555.12) U4.M7@1267.72,1535.43
  MidLayer4 w5: v1(1047.24,2031.5) 1031.5,2015.75 1031.5,1929.13 1043.31,1917.32 1043.31,1614.17 1082.68,1574.8 1228.35,1574.8 v1(1248.03,1555.12)
  Bottom Layer w5: R9.2@1015.75,2030 1017.25,2031.5 v1(1047.24,2031.5)
TMS: R6.2 U4.L8 | length 981.7
  Top Layer w7.87: v1(1287.4,1594.49) U4.L8@1307.09,1574.8
  MidLayer4 w5: v1(870.08,2102.36) 905.51,2066.93 1047.24,2066.93 1070.87,2043.31 1070.87,1933.07 1055.12,1917.32 1055.12,1637.79 1078.74,1614.17 1267.72,1614.17 v1(1287.4,1594.49)
  Bottom Layer w5: v1(870.08,2102.36) 901.57,2102.36 913.38,2114.17 R6.2@913.38,2132.36
TOFF: R23.1 U5.7 | length 159.5
  Top Layer w15.75: U5.7@2824.58,1783.25 2824.8,1783.46 2874.02,1783.46 2905.51,1814.96 R23.1@2970.94,1814.96
VCCA_PLL1: C108.1 C109.1 C110.1 C111.1 L1.2 U4.AA8 | length 494.9
  Top Layer w7.87: v1(1287.4,1161.41) U4.AA8@1307.09,1181.1
  MidLayer3 w5: v1(1248.03,901.57) 1267.72,921.26 1267.72,1141.73 v1(1287.4,1161.41)
  Bottom Layer w5: C110.1@1216.53,894.68 1248.03,894.68 C109.1@1279.52,894.68 ; C108.1@1342.52,894.68 C111.1@1397.63,909.45 L1.2@1397.63,838.58
  other v1: 1311.02,901.57
VCCA_PLL2: C112.1 C113.1 C114.1 C115.1 L2.2 U4.G19 | length 158.7
  Top Layer w7.87: U4.G19@1740.16,1732.28 v1(1759.84,1751.97)
  Bottom Layer w5: L2.2@1665.35,2106.29 C115.1@1700.78,2035.43 C112.1@1751.97,2042.32
  other v1: 1783.46,2043.31 1846.46,2043.31
VCCA_PLL3: C116.1 C117.1 C118.1 C119.1 L3.2 U4.G8 | length 148.7
  Top Layer w7.87: v1(1287.4,1751.97) U4.G8@1307.09,1732.28
  Bottom Layer w5: C116.1@1303.15,2038.38 C119.1@1350.39,2035.43 L3.2@1370.08,2106.29
  other v1: 1208.66,2043.31 1271.65,2047.24
VCCA_PLL4: C120.1 C121.1 C122.1 C123.1 L4.2 U4.AA19 | length 150.8
  Top Layer w7.87: U4.AA19@1740.16,1181.1 v1(1759.84,1161.41)
  Bottom Layer w5: L4.2@1645.67,893.7 C123.1@1700.78,917.32 ; C121.1@1814.96,910.43 1846.46,910.43 C122.1@1877.95,910.43
  other v1: 1783.46,909.45 1846.46,909.45
VFILT: C126.1 C127.1 R19.2 U5.5 U5.12 | length 544.3
  Top Layer w15.75: R19.2@2492.12,1643.23 2492.12,1688.98 C127.1@2488.18,1692.91 2488.19,1716.54 2504.9,1733.25 U5.12@2592.58,1733.25 ; U5.12@2592.58,1733.25 U5.5@2824.58,1733.25 2904.53,1733.27 2918.31,1719.48 C126.1@2944.88,1719.48
pads on no net: HDR_B1.93 HDR_B1.95 HDR_B1.MH5 HDR_B1.MH6 HDR_L1.MH5 HDR_L1.MH6 HDR_T1.95 HDR_T1.MH5 HDR_T1.MH6 MH1.MOUNT MH2.MOUNT MH3.MOUNT U1.5 U2.1 U3.A1 U3.A8 U3.B1 U3.B4 U3.C1 U3.D1 U3.E1 U3.F8 U3.G1 U3.G8 U3.H1 U3.H8 U4.A19 U4.AA3 U4.AA4 U4.AB3 U4.AB4 U4.AC3 U4.AC24 U4.AD3 U4.AE13 U4.B2 U4.B12 U4.B14 U4.B25 U4.C8 U4.C19 U4.C21 U4.D3 U4.D12 U4.D18 U4.E5 U4.F4 U4.F6 U4.F24 U4.FID1 U4.G23 U4.G24 U4.H10 U4.H15 U4.H16 U4.J7 U4.J9 U4.J10 U4.K16 U4.K17 U4.K18 U4.K19 U4.K26 U4.L24 U4.M22 U4.M25 U4.N18 U4.N20 U4.N21 U4.N24 U4.T7 U4.T10 U4.U7 U4.U10 U4.V3 U4.W4 U4.Y2 U4.Y3 U4.Y4 U4.Y22 U6.40 U7.40
copper on no net: | length 7320.2
  Top Layer w5: 1464.57,1929.13 1484.25,1948.82 1484.25,2011.81 ; 1724.41,2031.5 1724.41,2000 1740.16,1984.25 1740.16,1968.51 ; 1976.38,1535.43 1996.06,1555.12 2023.62,1555.12 2031.5,1562.99 ; 2015.75,1614.17 2078.74,1614.17
  Top Layer w7.87: v1(1051.18,1948.82) 1070.87,1929.13 ; v1(1090.55,1043.3) 1110.24,1062.99 ; v1(1090.55,1082.67) 1110.24,1102.36 ; v1(1090.55,1122.04) 1110.24,1141.73 ; v1(1090.55,1161.41) 1110.24,1181.1 ; v1(1090.55,1200.78) 1110.24,1220.47 ; v1(1090.55,1279.53) 1110.24,1299.21 ; v1(1090.55,1870.08) 1110.24,1850.39 ; v1(1129.92,1122.04) 1149.61,1141.73 ; v1(1129.92,1161.41) 1149.61,1181.1 ; v1(1129.92,1200.78) 1149.61,1220.47 ; v1(1129.92,1240.16) 1149.61,1259.84 ; v1(1129.92,1791.34) 1149.61,1771.65 ; v1(1169.29,1830.71) 1188.98,1811.02 ; v1(1208.66,1791.34) 1228.35,1771.65 ; v1(1248.03,1318.9) 1267.72,1338.58 ; v1(1248.03,1358.27) 1267.72,1377.95 ; v1(1248.03,1673.23) 1267.72,1653.54 ; v1(1287.4,1909.45) 1307.09,1889.76 ; v1(1444.88,1870.08) 1464.57,1850.39 ; 1582.68,1692.91 v1(1602.36,1712.6) ; 1622.05,1692.91 v1(1641.73,1712.6) ; 1661.42,1614.17 v1(1681.1,1633.86) ; 1700.79,1496.06 v1(1720.47,1515.75) ; 1700.79,1614.17 v1(1720.47,1633.86) ; 1700.79,1850.39 v1(1720.47,1870.08) ; 1740.16,1614.17 v1(1759.84,1633.86) ; 1740.16,1889.76 v1(1759.84,1909.45) ; 1779.53,1496.06 v1(1799.22,1515.75) ; 1818.9,1889.76 v1(1838.58,1909.45) ; 1858.27,1220.47 v1(1877.95,1200.78) ; 1858.27,1535.43 v1(1877.96,1555.12) ; 1937.01,1574.8 v1(1956.7,1594.49) ; 1937.01,1771.65 v1(1956.7,1791.34) ; 3149.61,4212.6 3149.61,4330.71
  MidLayer1 w5: 967.34,1175.04 1064.8,1175.04 1070.87,1181.1 1110.24,1181.1 v1(1129.92,1200.78) ; 967.75,1185.04 1051.18,1185.04 1066.93,1200.78 v1(1090.55,1200.78) ; 968.5,1023.62 1039.37,1023.62 1059.05,1043.3 v1(1090.55,1043.3) ; 968.5,1106.3 1070.87,1106.3 1074.8,1102.36 1110.24,1102.36 v1(1129.92,1122.04) ; 968.51,1122.04 v1(1090.55,1122.04) ; 968.5,1137.79 1066.93,1137.79 1070.87,1141.73 1110.24,1141.73 v1(1129.92,1161.41) ; 968.5,1153.54 1063,1153.54 1070.87,1161.41 v1(1090.55,1161.41) ; 968.5,1200.79 1043.31,1200.79 1062.99,1220.47 1110.24,1220.47 v1(1129.92,1240.16) ; 968.51,1279.53 v1(1090.55,1279.53) ; 1003.94,1062.99 1035.43,1062.99 1055.12,1082.67 v1(1090.55,1082.67) ; 1267.72,2015.75 1267.72,1956.69 1287.4,1937.01 v1(1287.4,1909.45) ; v1(1444.88,1870.08) 1464.57,1889.77 1464.57,1921.26 1476.38,1933.07 1476.38,2031.5 ; v1(1720.47,1870.08) 1740.16,1889.76 1740.16,1944.88 1728.35,1956.69 1728.35,2031.5 ; 1740.16,2031.5 1740.16,1968.5 1759.84,1948.82 v1(1759.84,1909.45) ; 1830.71,2031.5 1830.71,1937.01 1838.58,1929.13 v1(1838.58,1909.45) ; v1(1877.96,1555.12) 1897.64,1574.8 1992.13,1574.8 2031.5,1614.17 2078.74,1614.17 ; v1(1917.32,1751.97) 1937.01,1771.65 1976.38,1771.65 1992.13,1787.4 2078.74,1787.4 ; v1(1956.7,1594.49) 1984.25,1594.49 2015.75,1625.98 2078.74,1625.98 ; v1(1956.7,1791.34) 1976.38,1791.34 1984.25,1799.21 2078.74,1799.21
  MidLayer2 w5: v1(1090.55,1870.08) 1109.95,1889.48 1109.95,1920.15 ; v1(1799.22,1515.75) 1830.71,1484.25 2078.74,1484.25 ; v1(1877.95,1200.78) 1897.64,1181.1 2078.74,1181.1
  MidLayer3 w5: 1078.94,1811.02 1149.61,1811.02 v1(1169.29,1830.71) ; 1079.68,1850.39 1181.1,1850.39 1188.98,1842.52 1188.98,1811.02 v1(1208.66,1791.34)
  MidLayer4 w5: 968.51,1456.69 1338.58,1456.69 1346.46,1448.82 1346.46,1377.95 ; 1346.46,1377.95 v1(1366.14,1358.27) ; v1(1602.36,1712.6) 1582.68,1732.28 1582.68,1921.26 1653.54,1992.13 1653.54,2031.5 ; v1(1641.73,1712.6) 1622.05,1732.28 1622.05,1925.2 1669.29,1972.44 1669.29,2031.5 ; v1(1720.47,1515.75) 1740.16,1535.43 1976.38,1535.43 2035.43,1594.49 2078.74,1594.49 ; v1(1720.47,1633.86) 1720.47,1602.36 1748.03,1574.8 1972.44,1574.8 2011.81,1614.17 2078.74,1614.17 ; v1(1759.84,1633.86) 1779.53,1614.17 1964.32,1614.17 2011.56,1661.42 2078.74,1661.42
  other v1: 1618.11,43.31 1456.69,59.06 1771.65,59.06 1556.86,68.68 1679.36,68.68 1531.5,129.92 1704.72,129.92 1556.86,191.17 1679.36,191.17 1618.11,216.54 1366.14,1673.23 1366.14,1712.6 129.92,4240.16 3106.3,4240.16 68.68,4265.53 191.17,4265.53 3045.05,4265.53 3167.54,4265.53 43.31,4326.77 216.54,4326.77 3019.68,4326.77 3192.91,4326.77 68.68,4388.02 191.17,4388.02 3045.05,4388.02 3167.54,4388.02 129.92,4413.39 3106.3,4413.39

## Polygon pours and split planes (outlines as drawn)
AGND on Top Layer "AGND-TOP" (solid, remove dead copper, pour order 1016): 2377.61,2077.57 2377.61,1677.17 3088.3,1677.17 3088.3,2077.57
GND on Top Layer "GROUND-TOP-LAYER" (solid, remove dead copper, pour order 1017): 19.68,4132.62 298.72,4132.62 298.72,4409.45 2929.63,4409.45 2929.63,4132.62 3208.66,4132.62 3208.66,19.68 1813.48,19.68 1813.48,296.52 1414.86,296.52 1414.86,19.68 19.68,19.68
1V2 on MidLayer1 "FPGAPWR-ML1-1V2" (solid, pour order 1012): 1471.71,1858.42 1471.71,2031.95 1574.38,2031.95 1574.38,1854.79 1810.6,1854.79 1901.15,1764.24 1901.15,1524.08 2078.32,1524.08 2078.32,1425.65 1901.15,1425.65 1901.15,1189.43 1810.6,1098.88 1574.38,1098.88 1574.38,921.72 1472.02,921.72 1472.02,1098.88 1235.8,1098.88 1145.25,1189.43 1145.25,1425.65 968.08,1425.65 968.08,1528.01 1145.25,1528.01 1145.25,1772.11 1227.92,1854.79
GND on MidLayer1 "GROUND-MID1-LAYER" (solid, remove dead copper, pour order 1018): 19.68,4132.62 298.72,4132.62 298.72,4409.45 2929.63,4409.45 2929.63,4132.62 3208.66,4132.62 3208.66,19.68 1813.48,19.68 1813.48,296.52 1414.86,296.52 1414.86,19.68 19.68,19.68
1V2 on MidLayer1 "1V2-connect-to-L1-C17" (solid, remove dead copper, pour order 1014): 1893.7,1417.32 3133.86,1417.32 3133.86,2208.66 2375.98,2208.66 2375.98,1694.29 1893.7,1694.29
GND on MidLayer2 "GROUND-MID2-LAYER" (solid, remove dead copper, pour order 1019): 19.68,4132.62 298.72,4132.62 298.72,4409.45 2929.63,4409.45 2929.63,4132.62 3208.66,4132.62 3208.66,19.68 1813.48,19.68 1813.48,296.52 1414.86,296.52 1414.86,19.68 19.68,19.68
no net on MidLayer2 "VCCX" (solid, remove dead copper, pour order 1015): 2409.45,2322.83 3051.18,2322.83 3051.18,137.8 2409.45,137.8
VCCA_PLL1 on MidLayer3 "VCCA_PLL1_MID3" (solid, remove dead copper, pour order 1008): 1235,1181.1 1326.77,1181.1 1326.77,881.89 1224.41,881.89 1224.41,1181.1
VCCA_PLL3 on MidLayer3 "VCCA_PLL3_MID3" (solid, remove dead copper, pour order 1010): 1303.15,1736.22 1185.04,1736.22 1185.04,2055.12 1303.15,2055.12
GND on MidLayer3 "GROUND-MID3-LAYER" (solid, remove dead copper, pour order 1020): 19.68,4132.62 298.72,4132.62 298.72,4409.45 2929.63,4409.45 2929.63,4132.62 3208.66,4132.62 3208.66,19.68 1813.48,19.68 1813.48,296.52 1414.86,296.52 1414.86,19.68 19.68,19.68
VCCA_PLL4 on MidLayer4 "VCCA_PLL4_MID4" (solid, remove dead copper, pour order 1011): 1748.03,1181.1 1862.2,1181.1 1862.2,893.7 1751.49,893.7 1749.72,895.66 1748.03,897.53
VCCA_PLL2 on MidLayer4 "VCCA_PLL2_MID4" (solid, remove dead copper, pour order 1009): 1744.09,1736.22 1862.2,1736.22 1862.2,2062.99 1744.09,2062.99
GND on MidLayer4 "GROUND-MID4-LAYER" (solid, remove dead copper, pour order 1021): 19.68,4132.62 298.72,4132.62 298.72,4409.45 2929.63,4409.45 2929.63,4132.62 3208.66,4132.62 3208.66,19.68 1813.48,19.68 1813.48,296.52 1414.86,296.52 1414.86,19.68 19.68,19.68
1V2 on Bottom Layer "1V2-BL" (solid, remove dead copper, pour order 1000): 1433.07,2240.16 1433.07,2059.06 1602.36,2059.06 1602.36,2149.61 2559.06,2149.61 2559.06,2066.93 3070.87,2066.93 3070.87,2240.16
VCCA_PLL2 on Bottom Layer "VCCA_PLL2_BL" (solid, remove dead copper, pour order 1005): 1657.48,2145.67 1714.47,2145.67 1714.47,2065.58 1897.64,2065.58 1897.64,2023.62 1665.62,2023.62 1665.62,2057.95 1657.48,2057.95
GND on Bottom Layer "FPGAPWR-BL-GND" (solid, pour order 1001): 1417.32,1574.8 1623.11,1574.8 1623.11,1376.89 1417.32,1376.89
1V2 on Bottom Layer "FPGAPWR-BL-1V2" (solid, pour order 1002): 1224.41,1736.22 1224.41,1177.16 1818.9,1177.16 1818.9,1736.22
VCCA_PLL1 on Bottom Layer "VCCA_PLL1_BL" (solid, remove dead copper, pour order 1004): 1429.13,803.15 1429.13,933.07 1192.91,933.07 1192.91,881.89 1366.14,881.89 1366.14,803.15
VCCA_PLL4 on Bottom Layer "VCCA_PLL4_BL" (solid, remove dead copper, pour order 1007): 1901.57,932.68 1901.57,885.04 1666.7,885.04 1666.7,850.39 1618.11,850.39 1618.11,937.01 1901.57,937.01
VCCA_PLL3 on Bottom Layer "VCCA_PLL3_BL" (solid, remove dead copper, pour order 1006): 1389.76,2145.67 1334.65,2145.67 1334.65,2062.99 1157.48,2062.99 1157.48,2019.68 1381.89,2019.68 1381.89,2055.12 1389.76,2055.12
3V3 on Bottom Layer "FPGAPWR-BL-3V3" (solid, pour order 1003): 1083.33,1956.69 1979.86,1956.69 2003.88,1932.68 2003.88,1020.08 1979.86,996.06 1067.32,996.06 1043.31,1020.08 1043.31,1932.68 1067.32,1956.69
GND on Bottom Layer "GROUND-BOTTOM-LAYER" (solid, remove dead copper, pour order 1017): 19.68,4132.62 298.72,4132.62 298.72,4409.45 2929.63,4409.45 2929.63,4132.62 3208.66,4132.62 3208.66,19.68 1813.48,19.68 1813.48,296.52 1414.86,296.52 1414.86,19.68 19.68,19.68
GND on GND-Layer5 (split plane): 3216.12,4436.6 3216.12,20.1 20.1,20.1 20.1,4436.6 1523.62,4436.6
3V3 on VCC (split plane): 1523.62,4436.6 2701.84,4436.6 2701.84,4061.24 2702.17,4058.67 2703.17,4056.27 2704.74,4054.22 2720.98,4037.98 2721.87,4037.3 2723.04,4036.4 2725.43,4035.41 2728,4035.07 3041.89,4035.07 3106.07,3970.89 3106.07,2319.11 3064.6,2277.64 2921.43,2277.64 2802.3,2396.78 2800.24,2398.36 2797.84,2399.35 2795.28,2399.69 2629.92,2399.69 2627.35,2399.35 2624.96,2398.36 2622.9,2396.78 2617,2390.88 2615.42,2388.82 2614.43,2386.43 2614.09,2383.86 2614.09,2206.87 2429.99,2022.77 2428.41,2020.71 2427.42,2018.32 2427.08,2015.75 2427.08,1590.55 2427.42,1587.98 2428.41,1585.59 2429.99,1583.53 2445.74,1567.78 2447.79,1566.21 2450.19,1565.21 2452.76,1564.88 2582.68,1564.88 2585.25,1565.21 2587.64,1566.21 2589.7,1567.78 2618.29,1596.37 2712.19,1596.37 2725.07,1583.49 2725.07,1440 2725.41,1437.43 2726.4,1435.04 2727.98,1432.98 2732.98,1427.98 2735.04,1426.4 2737.43,1425.41 2740,1425.07 3005.77,1425.07 3045.19,1385.65 3045.19,1287.4 3045.19,1244.09 3045.19,795.45 2948.64,698.9 2838.58,698.9 2836.01,698.57 2833.62,697.57 2831.56,696 2780.38,644.82 2778.8,642.76 2777.81,640.36 2777.47,637.8 2777.47,523.8 2617,363.32 2615.42,361.26 2614.43,358.87 2614.09,356.3 2614.09,20.1 20.1,20.1 20.1,4436.6 1523.62,4436.6
5V0 on VCC (split plane): 3216.12,4436.6 3216.12,20.1 2633.94,20.1 2633.94,352.19 2794.42,512.67 2796,514.72 2796.99,517.12 2797.33,519.68 2797.33,633.68 2842.69,679.05 2952.76,679.05 2955.33,679.39 2957.72,680.38 2959.78,681.96 3062.14,784.32 3063.03,785.48 3063.72,786.37 3064.01,787.08 3064.71,788.77 3065.05,791.34 3065.05,1244.09 3065.05,1287.4 3065.05,1389.76 3064.71,1392.33 3063.72,1394.73 3062.82,1395.89 3062.14,1396.78 3016.9,1442.02 3014.85,1443.6 3012.45,1444.59 3009.88,1444.93 2744.93,1444.93 2744.93,1587.6 2744.59,1590.17 2743.6,1592.56 2742.02,1594.62 2723.32,1613.32 2721.26,1614.9 2718.87,1615.89 2716.3,1616.23 2614.17,1616.23 2611.6,1615.89 2609.21,1614.9 2607.15,1613.32 2578.57,1584.73 2456.87,1584.73 2446.94,1594.66 2446.94,2011.64 2631.04,2195.74 2632.61,2197.79 2633.6,2200.19 2633.94,2202.76 2633.94,2379.75 2634.03,2379.84 2791.16,2379.84 2910.3,2260.7 2911.2,2260.01 2912.36,2259.12 2914.75,2258.13 2917.32,2257.79 3068.72,2257.79 3071.29,2258.13 3073.68,2259.12 3075.74,2260.7 3123.02,2307.98 3124.6,2310.04 3125.59,2312.43 3125.93,2315 3125.93,3975 3125.59,3977.57 3124.6,3979.96 3123.7,3981.13 3123.02,3982.02 3053.02,4052.02 3050.96,4053.6 3048.57,4054.59 3046,4054.93 2732.11,4054.93 2721.69,4065.35 2721.69,4436.6

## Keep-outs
Bottom Layer:
  rectangle: 2643.7,3334.65 2840.55,3417.32
Keep-Out Layer:
  circle w15.75: c2928.82,2472.44 r118.11
  circle w15.75: c857.95,2472.44 r118.11
  circle w15.75: c306.77,2507.87 r118.11
  circle w15.75: c306.77,437.01 r118.11
  circle w15.75: c857.95,472.44 r118.11
  circle w15.75: c2928.82,472.44 r118.11
  region: 0,4456.69 0,4433.07 3236.22,4433.07 3236.22,4456.69
  rectangle: 0,0 3236.22,23.62
  rectangle: 0,0 23.62,4456.69
  region: 3236.22,4456.69 3212.6,4456.69 3212.6,0 3236.22,0
Mechanical 4:
  rectangle: 236.22,4358.27 925.2,4456.69

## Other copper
Top Layer:
  rectangle net GND: 3093.5,1773.6 3142.6,1785.4
  region net LX: 2768.7,1716.54 2645.67,1716.54 2645.67,1622.32 2768.7,1622.32
  rectangle net 5V0: 2645.67,2251.97 2740.16,2393.7
  rectangle net GND: 2645.67,2551.18 2740.16,2692.91
  rectangle net 1V2: 2850.39,2100 3027.56,2195
  rectangle net 5V0: 2881.48,1479.25 3013.03,1700.34
  rectangle net 5V0: 2824.06,1449.65 2951.2,1558.01
  rectangle net GND: 3011.8,1366.15 3031.49,1405.52
  pour cut-out: 2554.02,3195 2554.02,2865 2194.02,2865 2194.02,3195
  pour cut-out: 995.43,2007.56 2055.43,2007.56 2055.43,947.56 995.43,947.56
Bottom Layer:
  rectangle net LX: 2649.61,1614.17 2783.46,1724.41
  rectangle net 1V2: 2838.58,1964.57 3051.18,2200.79
  rectangle net 5V0: 2629.92,2248.03 2740.16,2346.46
  rectangle net 5V0: 2645.67,2248.03 2740.16,2346.46
  rectangle net 3V3: 2562.99,2570.86 2610.24,2704.72
  rectangle net 3V3: 2562.99,570.86 2610.24,704.72
  rectangle net GND: 2645.67,2598.43 2740.16,2696.85
  rectangle net 5V0: 2645.67,251.97 2740.16,346.46
  rectangle net GND: 2645.67,598.43 2740.16,696.85
  region net LX: 2455.79,1920.32 2455.79,2040.32 2305.79,2040.32 2305.79,1920.32
  rectangle net 1V2: 2641.13,1901.74 2787.4,2043.82
GND-Layer5 (plane layer: these items are gaps in the copper):
  text "GND" at 1645.67,437.01 h60
VCC (plane layer: these items are gaps in the copper):
  lines w19.68: 2624.02,0 2624.02,356.3 2787.4,519.68 2787.4,637.8 2838.58,688.98 2952.76,688.98 3055.12,791.34 3055.12,1244.09 3055.12,1287.4 3055.12,1389.76 3009.88,1435 2740,1435 2735,1440 2735,1587.6 2716.3,1606.3 2614.17,1606.3 2582.68,1574.8 2452.76,1574.8 2437.01,1590.55 2437.01,2015.75 2624.02,2202.76 2624.02,2383.86 2629.92,2389.76 2795.28,2389.76 2917.32,2267.72 3068.72,2267.72 3116,2315 3116,3975 3046,4045 2728,4045 2711.76,4061.24 2711.76,4456.69
  text "5V0" at 2791.34,1826.77 h60
  text "3V3" at 1657.48,437.01 h60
